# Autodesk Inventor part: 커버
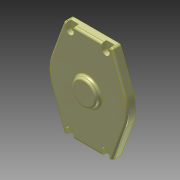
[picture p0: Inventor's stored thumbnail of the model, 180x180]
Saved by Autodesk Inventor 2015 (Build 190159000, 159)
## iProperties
Created: 2023-11
Part Number: 커버
Material: 알루미늄 6061
Document SubType Name: Modeling
Designer: mdu-01
Density: 1 g/cm^3
Appearance: 알루미늄 - 평지(1)
Author: mdu-01
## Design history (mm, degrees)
sketch "스케치1"
  geometry: L1 (-34.498, 66.026)-(-51.683, 18.811) reference; L2 (31.679, 68)-(-31.679, 68) reference; L3 (51.683, 18.811)-(34.498, 66.026) reference; L4 (-51.683, -18.811)-(-34.498, -66.026) reference; L5 (34.498, -66.026)-(51.683, -18.811) reference; L6 (-31.679, -68)-(31.679, -68) reference; C1 r 10 at (0, 0) reference; A1 r 3 centre (-31.679, 65) between (-31.679, 68) and (-34.498, 66.026) reference; A2 r 3 centre (31.679, 65) between (34.498, 66.026) and (31.679, 68) reference; A3 r 55 centre (0, 0) between (51.683, -18.811) and (51.683, 18.811) reference; A4 r 55 centre (0, 0) between (-51.683, 18.811) and (-51.683, -18.811) reference; A5 r 3 centre (-31.679, -65) between (-34.498, -66.026) and (-31.679, -68) reference; A6 r 3 centre (31.679, -65) between (31.679, -68) and (34.498, -66.026) reference; 1 further point
extrude "돌출1" new body sketch "스케치1" distance "d0" = 12; taper "d1" = 0 deg
sketch "스케치2"
  geometry: C1 r 10 at (0, 0) reference; 1 further point
extrude "돌출2" cut sketch "스케치2" distance "d2" = 10; taper "d3" = 0 deg
sketch "스케치3"
  geometry: C1 r 17.5 at (0, 0); 1 further point
  constraints: 1 centre point, 1 coincident
  dimensions: "d4" = 35 diameter of C1
extrude "돌출3" join sketch "스케치3" distance "d5" = 6; taper "d6" = 0 deg
fillet "모깎기1" dims "d7" = 3
sketch "스케치4"
  geometry: L1 (25, -61)-(-25, -61); L2 (-25, -61)-(-25, 61); L3 (-25, 61)-(25, 61); L4 (25, 61)-(25, -61); L5 (25, -61)-(-25, 61); L6 (-25, -61)-(25, 61); C1 r 2.458 at (-25, 61) reference; 1 further point
  constraints: 12 end point, 2 midpoint, 2 parallel, 1 coincident, 1 horizontal, 1 perpendicular
hole "구멍1" sketch "스케치4" at (-25, 61), (25, 61), (-25, -61), (25, -61) diameter "d8" = 6.6; stored, may be unused: countersink angle "d12" = 90 deg, drill point angle "d14" = 118 deg; dims "d9" = 6, "d10" = 11, "d11" = 6.6, "d13" = 8
sketch "스케치5"
  geometry: L1 (-30.5, 61)-(-19.5, 61); L2 (-19.5, 61)-(-19.5, 68); L3 (-19.5, 68)-(-30.5, 68); L4 (-30.5, 68)-(-30.5, 61); L5 (31.679, 68)-(-31.679, 68) reference; L6 (0, 0)-(0, 68); L7 (0, 0)-(-55, 0); L8 (19.5, 61)-(19.5, 68); L9 (19.5, 68)-(30.5, 68); L10 (30.5, 68)-(30.5, 61); L11 (30.5, 61)-(19.5, 61); L12 (19.5, -61)-(19.5, -68); L13 (19.5, -68)-(30.5, -68); L14 (30.5, -68)-(30.5, -61); L15 (30.5, -61)-(19.5, -61); L16 (-30.5, -68)-(-30.5, -61); L17 (-19.5, -68)-(-30.5, -68); L18 (-19.5, -61)-(-19.5, -68); L19 (-30.5, -61)-(-19.5, -61); A1 r 5.5 centre (-25, 61) between (-28.775, 65) and (-21.225, 65) reference; A2 r 55 centre (0, 0) between (-51.683, 18.811) and (-51.683, -18.811) reference
  constraints: 36 end point, 12 symmetric about line, 2 parallel, 2 point on circle, 2 tangent, 1 collinear, 1 horizontal, 1 midpoint, 1 perpendicular
extrude "돌출4" cut sketch "스케치5" stored distance "d15" = 6; taper "d16" = 0 deg
sketch "스케치6"
  geometry: L1 (10, 10)-(-10, 10) reference; L2 (7, 9.5)-(7, 2.044) reference; L3 (0, 10)-(0, 14.041); L4 (0, 14.041)-(7, 10); 1 further point
  constraints: 6 end point, 2 point on line, 1 midpoint, 1 parallel, 1 vertical, 2 other
  dimensions: "d17" = 60 deg angle of L3 L4
revolve "회전1" sketch "스케치6" stored, may be unused: angle "d18" = 90 deg
node "솔리드1"
node "참조1"
node "참조2"
node "참조3"
node "참조4"
node "참조5"
node "참조6"
node "참조7"
node "참조8"
node "참조9"
node "참조10"
node "참조11"
node "참조12"
node "참조13"
node "참조14"
